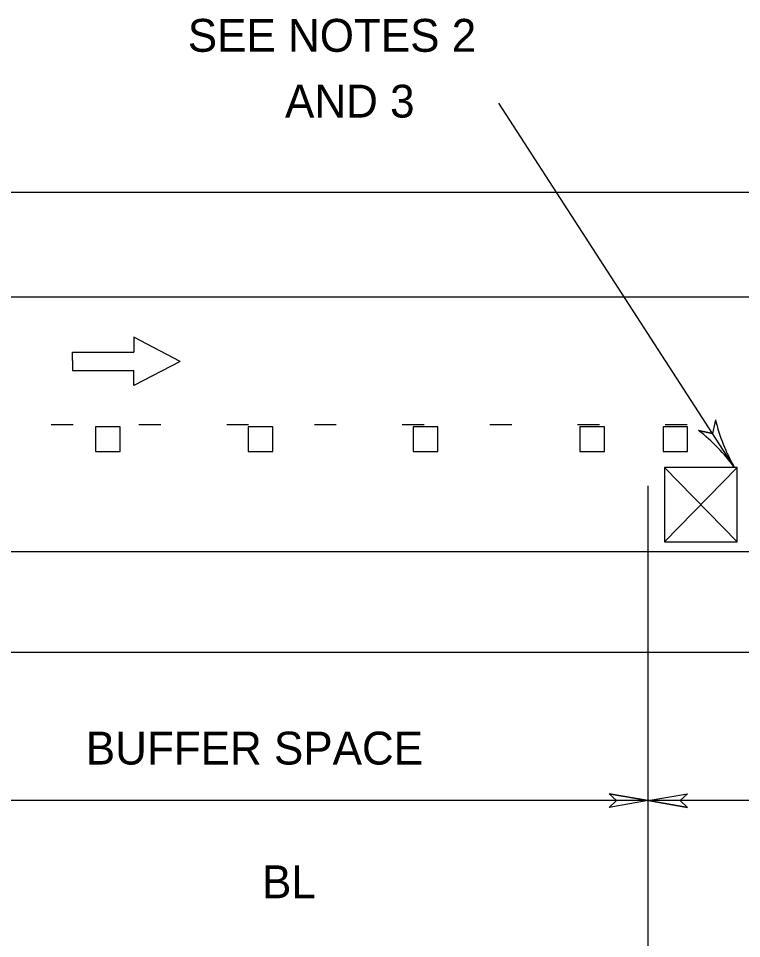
# Model space of a CAD drawing. Extents: x 12.4 to 19.6, y 4 to 16.
# Drawn here: x 15.682 to 17.002, y 10.241 to 11.919 of the extents above; entities that cross this region are included whole.
import ezdxf

# ---------------------------------------------------------------- set-up
doc = ezdxf.new("R2010")
doc.units = 0
for name, color, linetype in [('DETL-DIMS', 7, 'Continuous'), ('DETL-LINE', 7, 'Continuous'), ('DETL-NOTE', 7, 'Continuous'), ('MRKG-LINE', 7, 'Continuous'), ('USER-BORD', 7, 'Continuous'), ('V7_LEVEL_1', 7, 'Continuous')]:
    doc.layers.add(name, color=color, linetype=linetype)

# ---------------------------------------------------------------- blocks, each defined once
blk = doc.blocks.new('DIR2')
at = {"layer": 'USER-BORD'}
for p, q in [((0, 0.001), (-0.034, -0.048)), ((0, 0.001), (0.034, -0.048)), ((-0.034, -0.048), (-0.013, -0.048)), ((-0.013, -0.113), (-0.013, -0.048)), ((0.034, -0.048), (0.013, -0.048)), ((0.013, -0.113), (0.013, -0.048)), ((-0.001, -0.113), (-0.013, -0.113)), ((-0.001, -0.113), (0.001, -0.113)), ((0.001, -0.113), (0.013, -0.113))]:
    blk.add_line(p, q, dxfattribs=at)

msp = doc.modelspace()

# ---------------------------------------------------------------- linework, layer by layer
at = {"layer": 'DETL-DIMS'}
for p, q in [((16.8315, 8.348), (16.8315, 11.0669)), ((16.8315, 10.4922), (16.76, 10.5048)), ((16.76, 10.5048), (16.7735, 10.4922)), ((16.8315, 10.4922), (16.903, 10.5048)), ((16.8895, 10.4922), (16.903, 10.5048)), ((19.0458, 10.4922), (13.3764, 10.4922)), ((16.8315, 10.4922), (16.76, 10.4796)), ((16.7735, 10.4922), (16.76, 10.4796)), ((16.8315, 10.4922), (16.903, 10.4796)), ((16.903, 10.4796), (16.8895, 10.4922))]:
    msp.add_line(p, q, dxfattribs=at)
for points in [[(16.76, 10.5048), (16.8315, 10.4922), (16.76, 10.4796), (16.7735, 10.4922)], [(16.903, 10.4796), (16.8315, 10.4922), (16.903, 10.5048), (16.8895, 10.4922)]]:
    msp.add_lwpolyline(points, close=True, dxfattribs=at)
at = {"layer": 'DETL-NOTE'}
for p, q in [((16.9886, 11.1003), (16.5586, 11.7647)), ((16.954, 11.1872), (16.9488, 11.1618)), ((16.9234, 11.1675), (16.9488, 11.1618)), ((16.9488, 11.1618), (16.9234, 11.1675))]:
    msp.add_line(p, q, dxfattribs=at)
for centre, start, end in [((17.2612, 11.2591), 193.1562, 210.226), ((16.7321, 10.9166), 35.5976, 52.6674)]:
    msp.add_arc(centre, 0.3154, start, end, dxfattribs=at)
at = {"layer": 'MRKG-LINE'}
for p, q in [((19.5024, 11.6019), (12.7024, 11.6019)), ((19.5024, 11.411), (12.7024, 11.411)), ((15.7824, 11.1781), (15.7424, 11.1781)), ((15.9424, 11.1781), (15.9024, 11.1781)), ((16.1024, 11.1781), (16.0624, 11.1781)), ((16.2624, 11.1781), (16.2224, 11.1781)), ((16.4224, 11.1781), (16.3824, 11.1781)), ((16.5824, 11.1781), (16.5424, 11.1781)), ((16.7424, 11.1781), (16.7024, 11.1781)), ((16.9024, 11.1781), (16.8624, 11.1781)), ((16.9024, 11.1781), (16.8624, 11.1781)), ((16.9024, 11.1781), (16.8624, 11.1781)), ((19.5024, 10.9461), (12.7024, 10.9461)), ((19.5024, 10.7623), (12.7024, 10.7623))]:
    msp.add_line(p, q, dxfattribs=at)
for points in [[(15.8233, 11.1741), (15.8233, 11.1293), (15.8681, 11.1293), (15.8681, 11.1741)], [(16.1017, 11.1741), (16.1017, 11.1293), (16.1465, 11.1293), (16.1465, 11.1741)], [(16.4027, 11.1741), (16.4027, 11.1293), (16.4475, 11.1293), (16.4475, 11.1741)], [(16.7069, 11.1741), (16.7069, 11.1293), (16.7517, 11.1293), (16.7517, 11.1741)], [(16.8584, 11.1741), (16.8584, 11.1293), (16.9032, 11.1293), (16.9032, 11.1741)]]:
    msp.add_lwpolyline(points, close=True, dxfattribs=at)
at = {"layer": 'V7_LEVEL_1'}
for p, q in [((16.9936, 11.0999), (16.8613, 11.0999)), ((16.8613, 11.0999), (16.8613, 10.9647)), ((16.9936, 11.0999), (16.8613, 10.9647)), ((16.8613, 11.0999), (16.9936, 10.9647)), ((16.9936, 10.9647), (16.9936, 11.0999)), ((16.8613, 10.9647), (16.9936, 10.9647))]:
    msp.add_line(p, q, dxfattribs=at)

# ---------------------------------------------------------------- block references
at = {"layer": 'DETL-LINE', "xscale": 1.2917647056, "yscale": 1.7223529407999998, "rotation": -90.00000000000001}
msp.add_blockref('DIR2', (15.9757, 11.2937), dxfattribs=at)

# ---------------------------------------------------------------- texts
at = {"layer": 'DETL-NOTE'}
for s, p in [('SEE NOTES 2', (15.9914, 11.8585)), (' AND 3', (16.1465, 11.7385))]:
    msp.add_text(s, height=0.06, dxfattribs=at).set_placement(p)
for s, p in [('BUFFER SPACE', (15.8054, 10.5581)), ('BL', (16.1269, 10.3141))]:
    msp.add_text(s, height=0.06, rotation=360, dxfattribs=at).set_placement(p)

doc.saveas('drawing.dxf')
